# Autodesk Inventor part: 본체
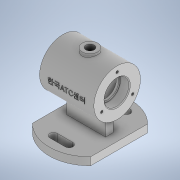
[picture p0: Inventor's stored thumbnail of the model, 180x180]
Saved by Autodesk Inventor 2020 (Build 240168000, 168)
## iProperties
Created: 2021-09
Part Number: 본체
Material: 일반
Document SubType Name: Modeling
Designer: Administrator
Density: 1 g/cm^3
Appearance: 기본값
Author: Administrator
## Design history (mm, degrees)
sketch "스케치1"
  geometry: L1 (-37.5, -62.928)-(37.5, -62.928); L2 (37.5, -62.928)-(37.5, 62.928); L3 (37.5, 62.928)-(-37.5, 62.928); L4 (-37.5, 62.928)-(-37.5, -62.928); L5 (-37.5, -62.928)-(37.5, 62.928); L6 (37.5, -62.928)-(-37.5, 62.928); C1 r 52.5 at (0, 0); 5 further points
  constraints: 12 end point, 2 midpoint, 2 parallel, 1 centre point, 1 coincident, 1 horizontal, 1 perpendicular
  dimensions: "d0" = 105 diameter of C1; "d1" = 75 distance of L2.end L3.end
extrude "돌출1" new body sketch "스케치1" distance "d2" = 10; taper "d3" = 0 deg
sketch "스케치2"
  geometry: L1 (36.742, 0)-(-36.742, 0) reference; C1 r 30 at (0, 62); 2 further points
  constraints: 1 centre point, 1 midpoint, 1 vertical alignment
  dimensions: "d4" = 62 distance from line of C1.centre L1; "d5" = 60 diameter of C1
extrude "돌출2" join sketch "스케치2" stored distance "d6" = 70; taper "d7" = 0 deg
node "작업 평면1"
sketch "스케치3"
  geometry: C1 r 10 at (0, 0); 1 further point
  constraints: 1 centre point, 1 coincident
  dimensions: "d9" = 20 diameter of C1
extrude "돌출3" join sketch "스케치3" stored distance "d10" = 70; taper "d11" = 0 deg; dims "d15" = 12, "d16" = 40, "d17" = 12, "d18" = 32, "d19" = 28, "d20" = 3, "d21" = 50
sketch "스케치4"
  geometry: L1 (25, 5.965)-(-25, 5.965); L2 (-25, 5.965)-(-25, 55.287); L3 (-25, 55.287)-(25, 55.287); L4 (25, 55.287)-(25, 5.965); L5 (25, 5.965)-(-25, 55.287); L6 (-25, 5.965)-(25, 55.287); 2 further points
  constraints: 12 end point, 2 midpoint, 2 parallel, 1 horizontal, 1 perpendicular
  dimensions: "d12" = 50 distance of L1.start L1.end
extrude "돌출4" join sketch "스케치4" stored distance "d13" = 10; taper "d14" = 0 deg
sketch "스케치5"
  geometry: L1 (35, 32)-(35, 92) reference; L2 (35, 62)-(-43.951, 62); L3 (-35, 92)-(-35, 32) reference; L4 (35, 78)-(23, 78); L5 (23, 78)-(23, 76); L6 (23, 76)-(20, 76); L7 (20, 76)-(20, 87); L8 (20, 87)-(-20, 87); L9 (-20, 87)-(-20, 76); L10 (-20, 76)-(-23, 76); L11 (-23, 76)-(-23, 78); L12 (-23, 78)-(-35, 78); 2 further points
  constraints: 20 end point, 6 perpendicular, 5 point on line, 3 horizontal, 1 midpoint
  dimensions: "d15" = 12 distance of L4.start L4.end; "d16" = 40 distance of L7.end L8.end; "d17" = 12 distance of L11.end L12.end; "d18" = 32 diameter of L4 L2; "d19" = 28 diameter of L6 L2; "d20" = 3 distance of L5.end L6.end; "d21" = 50 diameter of L8 L2
revolve "회전1" sketch "스케치5" stored, may be unused: angle "d22" = 90 deg
chamfer "모따기1" distance "d23" = 1; stored, may be unused: second distance "d24" = 2, angle "d25" = 45 deg
fillet "모깎기1" dims "d26" = 0.3
fillet "모깎기2" dims "d27" = 3
sketch "스케치6"
  geometry: C1 r 30 at (0, 0) reference; 2 further points
  constraints: 1 horizontal alignment
  dimensions: "d28" = 23 distance of point (-23, 0) C1.centre
hole "구멍1" sketch "스케치6" at (-23, 0) diameter "d29" = 3.242; stored, may be unused: countersink angle "d33" = 90 deg, drill point angle "d35" = 118 deg; dims "d30" = 8, "d31" = 4, "d32" = 2, "d34" = 10
sketch "스케치7"
  geometry: C1 r 10 at (0, 0) reference; 2 further points
  constraints: 1 coincident
hole "구멍2" sketch "스케치7" at (0, 0) diameter "d39" = 10.917; stored, may be unused: countersink angle "d43" = 90 deg, drill point angle "d45" = 118 deg; dims "d40" = 24, "d41" = 4, "d42" = 2, "d44" = 29.1
sketch "스케치8"
  geometry: L1 (-10, 37)-(10, 37); L2 (-10, 32)-(10, 32); L3 (10, 42)-(-10, 42); L4 (-10, -37)-(10, -37); L5 (-10, -42)-(10, -42); L6 (10, -32)-(-10, -32); A1 r 5 centre (-10, 37) between (-10, 42) and (-10, 32); A2 r 5 centre (10, 37) between (10, 32) and (10, 42); A3 r 5 centre (-10, -37) between (-10, -32) and (-10, -42); A4 r 5 centre (10, -37) between (10, -42) and (10, -32); 3 further points
  constraints: 16 end point, 8 point on circle, 8 tangent, 4 centre point, 3 parallel, 3 vertical alignment, 2 midpoint, 1 horizontal
  dimensions: "d46" = 20 distance of L1.end L1.start; "d47" = 5 radius of A1; "d48" = 5 radius of A3; "d49" = 37 vertical distance of point (0, 0) L1.start; "d50" = 37 vertical distance of L4.start point (0, 0)
extrude "돌출5" cut sketch "스케치8" extent not by distance; stored distance "d51" = 0; taper "d52" = 0 deg
node "작업 평면2"
sketch "스케치9"
  geometry: L1 (-35, 92)-(-35, 32) reference; 2 further points
  constraints: 1 other
  dimensions: "d54" = 35 distance from line of point (0, 62) L1; "d55" = 30 vertical distance of point (0, 62) L1.start
feature "엠보싱1" sketch "스케치9" dims "d0" = 105, "d1" = 75, "d56" = 0.5, "d57" = 0
node "솔리드1"
pattern_circular "원형 패턴1" dims angle "d37" = 360 deg
mirror "미러1"
feature "A9D066F2-1C7D-4E18-AEED-F7BC21143FA4" dims "d29" = 3.242, "d30" = 8, "d31" = 4, "d32" = 2, "d33" = 90 deg, "d34" = 10, "d35" = 118 deg
other parameters: "d8" = 95, "d53" = 77.75
